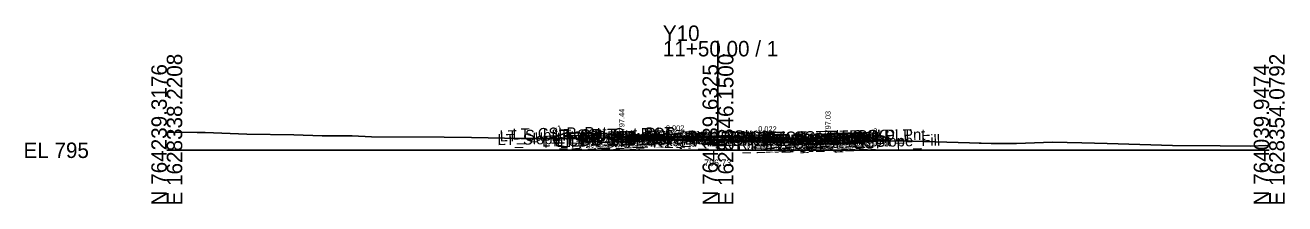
# Model space of a CAD drawing. Extents: x -26 to 203, y -10 to 4017.
# Drawn here: x -25.7 to 202.8, y 2990.3 to 3022.7 of the extents above; entities that cross this region are included whole.
import ezdxf

# ---------------------------------------------------------------- set-up
doc = ezdxf.new("R2010")
doc.units = 0
for name, color, linetype in [('Default', 7, 'Continuous'), ('Exist CMT Pavement', 7, 'Continuous'), ('Exist Cross Section Cell', 7, 'Continuous'), ('Exist XS Center Line Elevation Label', 7, 'Continuous'), ('Exist XS Ground Line', 7, 'Continuous'), ('Prop CMT Conc Surface', 7, 'Continuous'), ('Prop CMT Concrete Structures', 7, 'Continuous'), ('Prop CMT Pvmt Course 1', 7, 'Continuous'), ('Prop CMT Pvmt Course 1 CG', 7, 'Continuous'), ('Prop CMT Pvmt Course 1 Wedge', 7, 'Continuous'), ('Prop CMT Pvmt Course 2', 7, 'Continuous'), ('Prop CMT Pvmt Course 2 Wedge', 7, 'Continuous'), ('Prop CMT Pvmt Course 3', 7, 'Continuous'), ('Prop CMT Pvmt Course 3 Wedge', 7, 'Continuous'), ('Prop CMT Pvmt Surface', 7, 'Continuous'), ('Prop CMT Pvmt Wedge Surface 1', 7, 'Continuous'), ('Prop CMT Pvmt Wedge Surface 2', 7, 'Continuous'), ('Prop CMT Pvmt Wedge Surface 3', 7, 'Continuous'), ('Prop CMT Slope Grass', 7, 'Continuous'), ('Prop CMT Subgrade Earthwork', 7, 'Continuous'), ('Prop XS Hydro Elevations', 7, 'Continuous'), ('Prop XS SE Text', 7, 'Continuous'), ('Prop XS Side Slope Text', 7, 'Continuous'), ('Scratch_Level_0', 7, 'Continuous')]:
    doc.layers.add(name, color=color, linetype=linetype)

msp = doc.modelspace()

# ---------------------------------------------------------------- linework, layer by layer
at = {"layer": 'Exist CMT Pavement'}
for points in [[(100, 3001.73), (91.96, 3001.81), (85.72, 3001.87)], [(100, 3001.73), (102.4, 3001.71), (114.81, 3001.29), (114.98, 3001.28), (115.99, 3001.23)], [(115.99, 3001.23), (115.99, 3001.23)]]:
    msp.add_lwpolyline(points, dxfattribs=at)
at = {"layer": 'Exist Cross Section Cell'}
for p, q in [((100, 3000), (100, 3019.81)), ((0, 3000), (100, 3000)), ((100, 3000), (200, 3000))]:
    msp.add_line(p, q, dxfattribs=at)
at = {"layer": 'Exist XS Ground Line'}
msp.add_lwpolyline([(0, 3003.27), (5.48, 3003.21), (6.93, 3003.23), (14.52, 3002.9), (23.04, 3002.82), (28.18, 3002.64), (32.44, 3002.62), (33.25, 3002.62), (33.66, 3002.6), (37.12, 3002.41), (50.34, 3002.35), (55.29, 3002.31), (64.31, 3002.12), (70.28, 3002.11), (72.85, 3002.07), (75.05, 3002.19), (75.71, 3002.2), (81.32, 3002.26), (83.06, 3002.36), (84.47, 3002.29), (85.09, 3001.86), (85.72, 3001.87), (91.96, 3001.81), (100, 3001.73), (102.4, 3001.71), (114.98, 3001.28), (115.99, 3001.23), (117.44, 3001.71), (117.88, 3001.78), (119.18, 3001.8), (119.93, 3001.81), (126.11, 3001.59), (127.37, 3001.57), (128.78, 3001.62), (133.31, 3001.7), (145.63, 3001.33), (147.36, 3001.28), (147.75, 3001.3), (149.58, 3001.2), (154.17, 3001.2), (160.72, 3001.46), (166.04, 3001.32), (170.59, 3001.25), (182.48, 3000.87), (191.13, 3000.81), (196.68, 3000.75), (199.37, 3000.86), (200, 3000.83)], dxfattribs=at)
at = {"layer": 'Prop CMT Conc Surface'}
for points in [[(82.53, 3002.44), (82.53, 3002.94), (82.03, 3002.94)], [(84.53, 3002.52), (82.53, 3002.44)], [(117.96, 3002.16), (119.96, 3002.03)], [(119.96, 3002.03), (119.96, 3002.53), (120.46, 3002.53)]]:
    msp.add_lwpolyline(points, dxfattribs=at)
at = {"layer": 'Prop CMT Concrete Structures'}
for points in [[(84.53, 3002.52), (82.53, 3002.44), (82.53, 3002.94), (82.03, 3002.94)], [(82.03, 3002.94), (82.03, 3001.93), (84.53, 3001.94)], [(84.53, 3001.94), (84.53, 3002.52)], [(117.96, 3002.16), (119.96, 3002.03), (119.96, 3002.53), (120.46, 3002.53)], [(120.46, 3002.53), (120.46, 3001.52), (117.96, 3001.57)], [(117.96, 3001.57), (117.96, 3002.16)]]:
    msp.add_lwpolyline(points, dxfattribs=at)
at = {"layer": 'Prop CMT Pvmt Course 1'}
for points in [[(100, 3002.54), (84.53, 3002.52)], [(84.53, 3002.52), (84.53, 3002.27)], [(84.53, 3002.27), (85.72, 3002.27)], [(85.72, 3002.4), (100, 3002.42)], [(85.72, 3002.27), (85.72, 3002.4)], [(100, 3002.29), (100, 3002.54)], [(100, 3002.54), (117.96, 3002.16)], [(100, 3002.29), (100, 3002.54)], [(100, 3002.42), (100, 3002.29), (100, 3002.29)], [(115.99, 3002.07), (100, 3002.42)], [(100, 3002.42), (100, 3002.29), (100, 3002.29)], [(115.99, 3001.95), (115.99, 3002.07)], [(117.96, 3001.91), (115.99, 3001.95)], [(117.96, 3002.16), (117.96, 3001.91)]]:
    msp.add_lwpolyline(points, dxfattribs=at)
at = {"layer": 'Prop CMT Pvmt Course 1 CG'}
for points in [[(84.53, 3001.94), (81.53, 3001.93), (81.2, 3001.6)], [(81.2, 3001.6), (84.53, 3001.6)], [(84.53, 3001.6), (84.53, 3001.94)], [(117.96, 3001.57), (120.96, 3001.51), (121.3, 3001.17)], [(117.96, 3001.24), (117.96, 3001.57)], [(121.3, 3001.17), (117.96, 3001.24)]]:
    msp.add_lwpolyline(points, dxfattribs=at)
at = {"layer": 'Prop CMT Pvmt Course 1 Wedge'}
for points in [[(85.72, 3002.4), (91.96, 3002.41), (100, 3002.42)], [(85.72, 3002.27), (85.72, 3002.4)], [(100, 3002.29), (91.96, 3002.28), (85.72, 3002.27)], [(100, 3002.42), (100, 3002.29)], [(100, 3002.42), (102.4, 3002.37), (114.81, 3002.1), (114.98, 3002.1), (115.99, 3002.07)], [(100, 3002.29), (100, 3002.42)], [(115.99, 3001.95), (114.98, 3001.97), (114.81, 3001.97), (102.4, 3002.24), (100, 3002.29)], [(115.99, 3002.07), (115.99, 3001.95), (115.99, 3001.95)]]:
    msp.add_lwpolyline(points, dxfattribs=at)
at = {"layer": 'Prop CMT Pvmt Course 2'}
for points in [[(85.72, 3002.27), (84.53, 3002.27)], [(84.53, 3002.27), (84.53, 3001.94)], [(84.53, 3001.94), (85.72, 3001.94)], [(85.72, 3001.94), (85.72, 3002.27)], [(115.99, 3001.62), (115.99, 3001.95)], [(115.99, 3001.95), (117.96, 3001.91)], [(117.96, 3001.57), (115.99, 3001.62)], [(117.96, 3001.91), (117.96, 3001.57)]]:
    msp.add_lwpolyline(points, dxfattribs=at)
at = {"layer": 'Prop CMT Pvmt Course 2 Wedge'}
for points in [[(85.72, 3002.27), (91.96, 3002.28), (100, 3002.29)], [(85.72, 3001.94), (85.72, 3002.27)], [(100, 3001.96), (91.96, 3001.95), (85.72, 3001.94)], [(100, 3002.29), (100, 3001.96)], [(100, 3002.29), (102.4, 3002.24), (114.81, 3001.97), (114.98, 3001.97), (115.99, 3001.95)], [(100, 3001.96), (100, 3002.29)], [(115.99, 3001.62), (114.98, 3001.64), (114.81, 3001.64), (102.4, 3001.91), (100, 3001.96)], [(115.99, 3001.95), (115.99, 3001.62), (115.99, 3001.62)]]:
    msp.add_lwpolyline(points, dxfattribs=at)
at = {"layer": 'Prop CMT Pvmt Course 3'}
for points in [[(85.72, 3001.94), (84.53, 3001.94)], [(84.53, 3001.94), (84.53, 3001.6)], [(84.53, 3001.6), (85.72, 3001.61)], [(85.72, 3001.61), (85.72, 3001.94)], [(115.99, 3001.62), (117.96, 3001.57)], [(115.99, 3001.28), (115.99, 3001.62)], [(117.96, 3001.24), (115.99, 3001.28)], [(117.96, 3001.57), (117.96, 3001.24)]]:
    msp.add_lwpolyline(points, dxfattribs=at)
at = {"layer": 'Prop CMT Pvmt Course 3 Wedge'}
for points in [[(85.72, 3001.94), (91.96, 3001.95), (100, 3001.96)], [(85.72, 3001.87), (85.72, 3001.94)], [(100, 3001.73), (91.96, 3001.81), (85.72, 3001.87)], [(100, 3001.96), (100, 3001.73)], [(100, 3001.96), (102.4, 3001.91), (114.81, 3001.64), (114.98, 3001.64), (115.99, 3001.62)], [(100, 3001.73), (100, 3001.96)], [(115.99, 3001.23), (114.98, 3001.28), (114.81, 3001.29), (102.4, 3001.71), (100, 3001.73)], [(115.99, 3001.62), (115.99, 3001.23), (115.99, 3001.23)]]:
    msp.add_lwpolyline(points, dxfattribs=at)
at = {"layer": 'Prop CMT Pvmt Surface'}
for points in [[(100, 3002.54), (84.53, 3002.52)], [(100, 3002.54), (117.96, 3002.16)]]:
    msp.add_lwpolyline(points, dxfattribs=at)
at = {"layer": 'Prop CMT Pvmt Wedge Surface 1'}
for points in [[(84.53, 3002.27), (84.53, 3002.52)], [(85.72, 3002.27), (84.53, 3002.27)], [(100, 3002.42), (85.72, 3002.4)], [(85.72, 3002.4), (85.72, 3002.27)], [(100, 3002.42), (115.99, 3002.07)], [(115.99, 3002.07), (115.99, 3001.95)], [(115.99, 3001.95), (117.96, 3001.91)], [(117.96, 3001.91), (117.96, 3002.16)]]:
    msp.add_lwpolyline(points, dxfattribs=at)
at = {"layer": 'Prop CMT Pvmt Wedge Surface 2'}
for points in [[(84.53, 3002.27), (84.53, 3002.52)], [(100, 3002.29), (84.53, 3002.27)], [(100, 3002.29), (117.96, 3001.91)], [(117.96, 3001.91), (117.96, 3002.16)]]:
    msp.add_lwpolyline(points, dxfattribs=at)
at = {"layer": 'Prop CMT Pvmt Wedge Surface 3'}
for points in [[(84.53, 3001.94), (84.53, 3002.52)], [(100, 3001.96), (84.53, 3001.94)], [(100, 3001.96), (117.96, 3001.57)], [(117.96, 3001.57), (117.96, 3002.16)]]:
    msp.add_lwpolyline(points, dxfattribs=at)
at = {"layer": 'Prop CMT Slope Grass'}
for points in [[(82.03, 3002.94), (72.53, 3003.13), (69.47, 3002.11)], [(120.46, 3002.53), (126.96, 3002.66)], [(126.96, 3002.66), (130.01, 3001.65)]]:
    msp.add_lwpolyline(points, dxfattribs=at)
at = {"layer": 'Prop CMT Subgrade Earthwork'}
for points in [[(84.53, 3001.6), (81.2, 3001.6), (79.82, 3002.98)], [(85.72, 3001.61), (84.53, 3001.6)], [(85.72, 3001.61), (85.74, 3001.87)], [(115.99, 3001.28), (115.97, 3001.23)], [(115.99, 3001.28), (117.96, 3001.24)], [(117.96, 3001.24), (121.3, 3001.17), (122.71, 3002.58)]]:
    msp.add_lwpolyline(points, dxfattribs=at)

# ---------------------------------------------------------------- texts
at = {"layer": 'Default'}
msp.add_text('-', height=0.0001, dxfattribs=at).set_placement((0, 3000))
at = {"layer": 'Exist Cross Section Cell'}
for s, p in [('Y10', (90, 3019.81)), ('11+50.00 / 1', (90, 3017.01)), ('EL 795', (-26, 2998.6))]:
    msp.add_text(s, height=2.8, dxfattribs=at).set_placement(p)
for s, p in [('E 1628338.2208', (2.8, 2990)), ('E 1628346.1500', (102.8, 2990)), ('E 1628354.0792', (202.8, 2990)), ('N 764239.3176', (0, 2990)), ('N 764139.6325', (100, 2990)), ('N 764039.9474', (200, 2990))]:
    msp.add_text(s, height=2.8, rotation=90, dxfattribs=at).set_placement(p)
at = {"layer": 'Exist XS Center Line Elevation Label'}
msp.add_text('796.73', height=1.2, dxfattribs=at).set_placement((97.5, 2997.13))
at = {"layer": 'Prop XS Hydro Elevations'}
for s, p in [('797.44', (83.03, 3003.44)), ('797.03', (120.46, 3003.03))]:
    msp.add_text(s, height=1, rotation=90, dxfattribs=at).set_placement(p)
at = {"layer": 'Prop XS SE Text'}
for s, rotation, p in [('0.002', 0.0881, (90.55, 3003.53)), ('0.022', 358.7661, (107.29, 3003.39))]:
    msp.add_text(s, height=1, rotation=rotation, dxfattribs=at).set_placement(p)
at = {"layer": 'Prop XS Side Slope Text'}
for rotation, p in [(18.4332, (70.01, 3003.08)), (341.5668, (127.98, 3003.11))]:
    msp.add_text('3:1', height=1, rotation=rotation, dxfattribs=at).set_placement(p)
at = {"layer": 'Scratch_Level_0'}
for s, p in [('LT_Slope_Fill', (60.02, 3000.92)), ('LT_Sub_Trench_Out_DLT', (60.41, 3001.59)), ('LT_CSLP_Pnt', (62.73, 3001.93)), ('LT_CG1_Shelf_Out', (68.11, 3000.66)), ('LT_CG_Top_Face', (69.81, 3001.68)), ('LT_CG_Top_BOC', (70.34, 3001.7)), ('LT_CG_Bot_BOC', (70.37, 3000.7)), ('LT_PV_Sub_Tie_Out', (70.71, 3000.57)), ('LT_CG_Top_Gut', (70.79, 3001.2)), ('LT_PV_OEEOP_EG', (73.29, 3000.62)), ('LT_CG_Bot_IE', (74.47, 3000.74)), ('LT_PV2_OEOT', (74.73, 3001.07)), ('LT_PV3_OEOT', (74.73, 3000.74)), ('LT_PV2_OEEOP', (75.05, 3001.06)), ('LT_PV3_OEEOP', (75.05, 3000.73)), ('LT_PV1_OEOT', (75.29, 3001.34)), ('LT_PV1_OEEOP', (75.62, 3001.19)), ('RT_PV_IEEOP_EG', (88.16, 3000.49)), ('LT_PV_IEEOP_EG', (88.21, 3000.49)), ('RT_PV2_IEEOP', (89.93, 3001.09)), ('RT_PV3_IEEOP', (89.93, 3000.76)), ('LT_PV2_IEEOP', (89.97, 3001.09)), ('LT_PV3_IEEOP', (89.97, 3000.76)), ('RT_PV1_IEEOP', (90.49, 3001.23)), ('LT_PV1_IEEOP', (90.54, 3001.23)), ('PV2_PGL', (93.93, 3001.17)), ('PV1_PGL', (94.49, 3001.43)), ('RT_Sub_Trench_Out_DLT', (103.25, 3001.19)), ('RT_PV2_OEEOP', (105.27, 3000.74)), ('RT_PV1_OEEOP', (105.84, 3000.87)), ('RT_CG_Top_Face', (107.19, 3001.28)), ('RT_PV2_OEOT', (108.1, 3000.71)), ('RT_CG_Top_Gut', (108.17, 3000.8)), ('RT_PV1_OEOT', (108.67, 3000.97)), ('RT_CG_Top_BOC', (108.72, 3001.3)), ('RT_CSLP_Pnt', (120.11, 3001.53)), ('RT_Slope_Fill', (123.53, 3000.51)), ('LT_Sub_OEOP', (71.33, 3000.4)), ('LT_Sub_OEOT', (74.63, 3000.41)), ('LT_Sub_OEEOP', (74.96, 3000.39)), ('RT_PV_Sub_Tie_Out', (100.89, 2999.93)), ('RT_PV_OEEOP_EG', (103.51, 2999.98)), ('RT_Sub_OEEOP', (105.17, 3000.07)), ('RT_PV3_OEEOP', (105.27, 3000.4)), ('RT_CG1_Shelf_Out', (107.48, 3000.24)), ('RT_CG_Bot_IE', (107.84, 3000.37)), ('RT_Sub_OEOT', (108.01, 3000.04)), ('RT_PV3_OEOT', (108.1, 3000.38)), ('RT_CG_Bot_BOC', (108.75, 3000.29)), ('RT_Sub_OEOP', (111.38, 2999.97))]:
    msp.add_text(s, height=2, rotation=1.1458, dxfattribs=at).set_placement(p)

doc.saveas('drawing.dxf')
